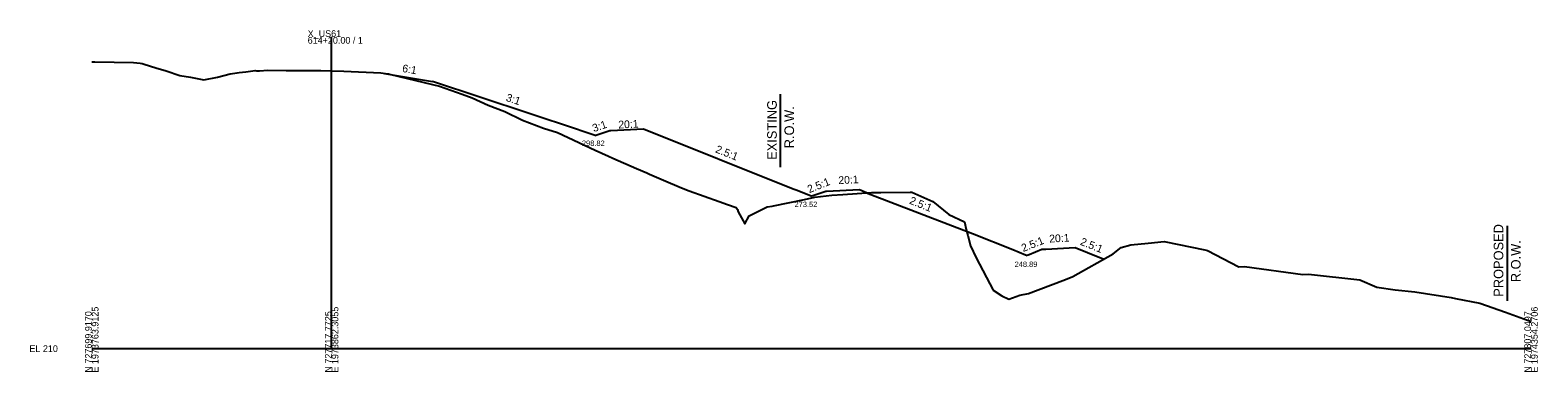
# Model space of a CAD drawing. Extents: x -26 to 1604, y -13 to 9623.
# Drawn here: x -26 to 603, y 5490 to 5633 of the extents above; entities that cross this region are included whole.
import ezdxf

# ---------------------------------------------------------------- set-up
doc = ezdxf.new("R2010")
doc.units = 0
for name, color, linetype in [('Draft_XS_Grid', 7, 'Continuous'), ('DTM CONTOURS_MAJOR', 7, 'Continuous'), ('DTM_X_GROUND', 7, 'Continuous'), ('SLOPE_STAKES_FILL', 7, 'Continuous'), ('XS_CELL', 7, 'Continuous'), ('XS_P_GROUND', 7, 'Continuous'), ('XS_P_ROW', 7, 'Continuous'), ('XS_P_TX_DCH', 7, 'Continuous'), ('XS_P_TX_FS_BS', 7, 'Continuous'), ('XS_X_ROW', 7, 'Continuous')]:
    doc.layers.add(name, color=color, linetype=linetype)

msp = doc.modelspace()

# ---------------------------------------------------------------- linework, layer by layer
at = {"layer": 'DTM_X_GROUND'}
msp.add_lwpolyline([(0, 5619.59), (1.21, 5619.57), (17.38, 5619.37), (20.14, 5619.03), (21.06, 5618.94), (21.8, 5618.69), (26.77, 5617.18), (30.98, 5615.85), (36.71, 5613.89), (41.15, 5613.2), (46.7, 5612.07), (52.41, 5613.16), (57.71, 5614.6), (60.56, 5614.99), (61.46, 5615.11), (64.27, 5615.49), (68.16, 5616.03), (68.73, 5615.91), (69.94, 5615.92), (73.44, 5616.1), (81.01, 5616.04), (93.43, 5615.96), (95.48, 5615.95), (99.99, 5615.92), (105.02, 5615.7), (120.45, 5615.02), (123.36, 5614.64), (123.64, 5614.6), (124.63, 5614.37), (144.99, 5609.52), (154.42, 5606.15), (158.62, 5604.61), (165.22, 5601.61), (172.13, 5598.91), (179.62, 5595.3), (188.25, 5591.95), (194.15, 5590.12), (209.92, 5582.74), (215.44, 5580.24), (217.24, 5579.48), (227.09, 5575.18), (231.37, 5573.3), (232.57, 5572.76), (239.3, 5569.81), (244.86, 5567.45), (247.21, 5566.53), (249.1, 5565.79), (255.23, 5563.63), (261.59, 5561.41), (265, 5560.18), (268.6, 5558.8), (269.25, 5558.06), (269.45, 5557.11), (272.3, 5552.03), (274, 5555.34), (281.55, 5559.14), (283.58, 5559.46), (284.26, 5559.6), (297.14, 5562.16), (301.42, 5563.16), (308.52, 5564.03), (313.1, 5564.22), (325.12, 5565.12), (328.99, 5565.14), (341.23, 5565.29), (341.62, 5565.31), (341.91, 5565.23), (350.61, 5561.31), (357.31, 5555.93), (363.89, 5552.87), (364.53, 5549.72), (365.19, 5547.18), (366.27, 5542.87), (368.71, 5537.91), (375.8, 5524.37), (379.43, 5522.04), (382.31, 5520.57), (386.89, 5522.34), (390.57, 5522.95), (404.79, 5528.47), (407.28, 5529.4), (409, 5530.14), (425.74, 5539.58), (429.16, 5542.16), (433.2, 5543.29), (440.33, 5543.99), (446.99, 5544.75), (464.01, 5541.14), (465.19, 5540.89), (478.15, 5534.11), (480.55, 5534.27), (504.84, 5530.92), (507.27, 5531.05), (528.61, 5528.67), (535.77, 5525.69), (543.35, 5524.56), (551.52, 5523.7), (566.67, 5521.29), (568.56, 5520.89), (578.6, 5519), (589.42, 5515.27), (600, 5511.3)], dxfattribs=at)
at = {"layer": 'XS_CELL'}
for p, q in [((100, 5500), (100, 5630)), ((0, 5500), (100, 5500)), ((100, 5500), (600, 5500))]:
    msp.add_line(p, q, dxfattribs=at)
at = {"layer": 'XS_P_GROUND'}
for points in [[(122, 5614.82), (142, 5611.48)], [(323.11, 5564.97), (322.94, 5565.04), (320, 5566.22), (306.34, 5565.53), (306, 5565.52), (300.15, 5563.57), (300, 5563.52), (299.85, 5563.58), (294, 5565.92), (292.43, 5566.55), (230, 5591.52), (216.34, 5590.83), (216, 5590.82), (210.15, 5588.87), (210, 5588.82), (209.85, 5588.87), (204, 5590.82), (202.48, 5591.33), (142, 5611.48)], [(322.94, 5565.04), (367.1, 5548.05), (384, 5541.29), (389.26, 5539.18), (390, 5538.89)], [(421.7, 5537.31), (420.2, 5537.91), (410, 5541.99), (397.72, 5541.37), (396, 5541.29), (390.74, 5539.18), (390, 5538.89)]]:
    msp.add_lwpolyline(points, dxfattribs=at)
at = {"layer": 'XS_P_ROW'}
msp.add_line((590, 5551.27), (590, 5520), dxfattribs=at)
at = {"layer": 'XS_X_ROW'}
msp.add_line((287, 5606.16), (287, 5575.62), dxfattribs=at)

# ---------------------------------------------------------------- texts
at = {"layer": 'Draft_XS_Grid'}
msp.add_text('-', height=0.0001, dxfattribs=at).set_placement((0, 5500))
at = {"layer": 'DTM CONTOURS_MAJOR'}
for p in [(383.96, 5541.23), (389.96, 5538.83), (389.96, 5538.83), (395.96, 5541.23), (409.96, 5541.93), (421.66, 5537.25)]:
    msp.add_text('X', height=0.12, dxfattribs=at).set_placement(p)
at = {"layer": 'SLOPE_STAKES_FILL'}
for p in [(141.96, 5611.42), (203.96, 5590.76), (209.96, 5588.76), (215.96, 5590.76), (229.96, 5591.46), (293.96, 5565.86), (299.96, 5563.46), (305.96, 5565.46), (319.96, 5566.16), (323.07, 5564.91)]:
    msp.add_text('X', height=0.12, dxfattribs=at).set_placement(p)
at = {"layer": 'XS_CELL'}
for s, p in [('X_US61', (90, 5630)), ('614+20.00 / 1', (90, 5627.2)), ('EL 210', (-26, 5498.6))]:
    msp.add_text(s, height=2.8, dxfattribs=at).set_placement(p)
for s, p in [('N 727699.9170', (0, 5490)), ('E 1973763.9125', (2.8, 5490)), ('N 727717.7725', (100, 5490)), ('E 1973862.3055', (102.8, 5490)), ('N 727807.0497', (600, 5490)), ('E 1974354.2706', (602.8, 5490))]:
    msp.add_text(s, height=2.8, rotation=90, dxfattribs=at).set_placement(p)
at = {"layer": 'XS_P_GROUND'}
msp.add_text('X', height=0.12, dxfattribs=at).set_placement((121.96, 5614.76))
at = {"layer": 'XS_P_ROW'}
for s, p in [('PROPOSED', (588.44, 5521.63)), ('R.O.W.', (595.64, 5527.7))]:
    msp.add_text(s, height=4, rotation=90, dxfattribs=at).set_placement(p)
at = {"layer": 'XS_P_TX_DCH'}
for s, p in [('298.82', (204.33, 5584.54)), ('273.52', (292.96, 5559.05)), ('248.89', (384.71, 5534.06))]:
    msp.add_text(s, height=2.25, dxfattribs=at).set_placement(p)
at = {"layer": 'XS_P_TX_FS_BS'}
for s, rotation, p in [('6:1', 350.53766, (129.25, 5615.42)), ('3:1', 341.56507, (172.38, 5603.41)), ('3:1', 18.43493, (209.3, 5590.29)), ('20:1', 2.86241, (219.57, 5591.78)), ('2.5:1', 338.19859, (259.7, 5581.95)), ('2.5:1', 21.80141, (299.11, 5564.82)), ('20:1', 2.86241, (311.3, 5568.6)), ('2.5:1', 338.19859, (340.56, 5560.56)), ('2.5:1', 21.80141, (388.3, 5540.27)), ('20:1', 2.86241, (399.21, 5544.23)), ('2.5:1', 338.19859, (411.77, 5543.41))]:
    msp.add_text(s, height=3.24, rotation=rotation, dxfattribs=at).set_placement(p)
at = {"layer": 'XS_X_ROW'}
for s, p in [('EXISTING', (285.56, 5578.73)), ('R.O.W.', (292.76, 5583.57))]:
    msp.add_text(s, height=4, rotation=90, dxfattribs=at).set_placement(p)

doc.saveas('drawing.dxf')
